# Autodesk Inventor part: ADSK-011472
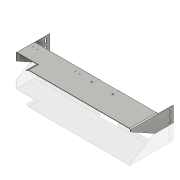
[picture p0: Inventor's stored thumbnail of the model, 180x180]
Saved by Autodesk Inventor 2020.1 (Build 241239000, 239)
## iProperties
Created: 2000-02
Part Number: ADSK-011472
Document SubType Name: Blech
Designer: gpurviance
Material: 1.0312 DC05
Mass: 487.517 g
Surface Area: 3339.23 cm^2
Volume: 487.517 cm^3
Density: 1 g/cm^3
Flat Pattern Width: 25.69 cm
Flat Pattern Length: 92.9572 cm
Flat Pattern Area: 2388.07 cm^2
Sheet Metal Rule: Stahlblech 1.0312 - DC05 -   3.0 mm
Sheet Metal Width: 256,900 mm
Sheet Metal Length: 929,572 mm
Sheet Metal Area: 238806,965 mm^2
Appearance: Stahl
Control State: 0
Master: False
Checked Out: False
Shininess: 60.0
Length Units: 11269
Angle Units: 11279
Time Units: 11290
Mass Units: 11283
Length Display Precision: 3
Angle Display Precision: 2
Compacted: True
Cutlength: 704 SI (20.25 X 34.75)
Material Desc: SHEET,HRS,11 GA
Material_Number: Axxxxxx
Dimensions: 746x97x256,9 mm
Mass: 0,488 kg
G_L: 929,6x256,9 mm
Thickness: 3,000 mm
Semi finished: Stahlblech 1.0312 - DC05 -   3.0 mm
Density: 0.0
Volumn: 0.0
Area: 0.0
PropertySet Name: Model Information
Author: gpurviance
Revision Number: -
Title: ADSK-011472
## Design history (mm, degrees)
node "Face1"
  sketch "Sketch2"
    geometry: L1 (0, 0)-(-746, 0); L2 (-746, 0)-(-746, -168); L3 (-746, -168)-(0, -168); L4 (0, -168)-(0, 0)
    constraints: 8 end point, 2 parallel, 1 horizontal, 1 perpendicular
    dimensions: "d1" = 168 distance between parallel lines of L3 L1; "d2" = 746 distance between parallel lines of L4 L2
node "Extrusion1" dims "d6" = 25.4, "d7" = 0
node "Lasche5"
node "Extrusion2" dims "d15" = 88.9, "d16" = 0
node "Lasche6"
feature "Eckenfase1" dims "d108" = 19, "d109" = 6.35, angle "d110" = 45 deg
node "Extrusion3" dims "d36" = 25.4, "d37" = 0
  sketch "Sketch9"
    geometry: L1 (0, 83.838)-(146, 2.838); L2 (236.9, 78.838)-(236.9, 59.838); L3 (226.9, 59.838)-(226.9, 78.838); L4 (236.9, 37.838)-(236.9, 18.838); L5 (226.9, 18.838)-(226.9, 37.838); L6 (231.9, 78.838)-(231.9, 59.838); L7 (231.9, 37.838)-(231.9, 18.838); L8 (0, 99.838)-(162, 99.838) reference; L9 (0, 2.837)-(0, 93.838) reference; L10 (0, 2.837)-(256.9, 2.838) reference; L11 (256.9, 2.838)-(256.9, 93.838) reference; A1 r 5 centre (231.9, 78.838) between (236.9, 78.838) and (226.9, 78.838); A2 r 5 centre (231.9, 59.838) between (226.9, 59.838) and (236.9, 59.838); A3 r 5 centre (231.9, 37.838) between (236.9, 37.838) and (226.9, 37.838); A4 r 5 centre (231.9, 18.838) between (226.9, 18.838) and (236.9, 18.838)
    constraints: 14 end point, 8 point on circle, 8 tangent, 4 centre point, 4 equal length, 2 point on line, 1 collinear, 1 equal radius
    dimensions: "d27" = 10 diameter of A2; "d38" = 19 distance of L7.start L7.end (= d39); "d39" = 19 distance of L6.start L6.end; "d111" = 16 distance from line of L8 L1.start; "d112" = 146 distance from line of L9 L1.end; "d113" = 25 distance between parallel lines of L11 L6; "d114" = 16 distance from line of L10 L7.end; "d115" = 22 distance of L7.start L6.end
node "Lasche7"
node "Hole1" dims "d48" = 4.134, "d49" = 9.525, "d50" = 6.35, "d51" = 60 deg, "d52" = 19.05, "d53" = 118 deg, "d131" = 10
node "Extrusion5" dims "d63" = 6 (= 2 x Thickness), "d64" = 0
node "Hole2" dims "d68" = 9, "d69" = 9.525, "d70" = 6.35, "d71" = 60 deg, "d72" = 19.05, "d73" = 118 deg, "d134" = 6
node "Volumenkörper1"
node "Volumenkörper"
node "Flächenkörper"
node "Plate1" dims "d87" = 3 (= Thickness)
sketch "Sketch3"
  geometry: L1 (0, 0)-(0, 168) reference; L2 (746, 0)-(0, 0) reference; L3 (0, 0)-(132, 0); L4 (132, 0)-(132, 57); L5 (132, 57)-(0, 57); L6 (0, 57)-(0, 0)
  constraints: 8 end point, 2 parallel, 1 horizontal, 1 perpendicular
  dimensions: "d4" = 132 distance between parallel lines of L1 L4; "d5" = 57 distance between parallel lines of L2 L5
sketch "Sketch6"
  geometry: L1 (-741.5, 93.838)-(-744.5, 93.838) reference; L2 (-744.5, 93.838)-(-744.5, 2.838) reference; L3 (-741.5, 2.838)-(-744.5, 2.838) reference; L4 (-741.5, 93.838)-(-741.5, 2.838) reference; L5 (1.5, 93.837)-(-1.5, 93.837) reference; L6 (-1.5, 93.837)-(-1.5, 2.837) reference; L7 (-1.5, 2.837)-(1.5, 2.837) reference; L8 (1.5, 2.837)-(1.5, 93.837) reference
node "FlatPattern"
sketch "Sketch11"
  geometry: L1 (-9.525, -101.75)-(-9.525, 3.25) reference; L2 (-3.525, 9.25)-(730.475, 9.25) reference; 4 further points
  constraints: 3 horizontal alignment
  dimensions: "d126" = 25 distance of point (42.475, -25.25) point (17.475, -25.25); "d127" = 25 distance of point (296.475, -25.25) point (271.475, -25.25) (= d126); "d128" = 27 distance from line of L1 point (17.475, -25.25); "d129" = 254 distance of point (271.475, -25.25) point (17.475, -25.25); "d130" = 34.5 distance from line of L2 point (17.475, -25.25)
sketch "Sketch13"
  geometry: L1 (209.112, 3.4)-(320.112, 3.4); L2 (320.112, 3.4)-(320.112, 28.4); L3 (320.112, 28.4)-(209.112, 28.4); L4 (209.112, 28.4)-(209.112, 3.4); L5 (-28.888, 22.4)-(-28.888, -68.6) reference; L6 (689.112, 3.4)-(-6.888, 3.4) reference; L7 (-25.888, 28.4)-(708.112, 28.4) reference
  constraints: 8 end point, 2 collinear, 2 parallel, 1 horizontal, 1 perpendicular
  dimensions: "d74" = 111 distance between parallel lines of L2 L4; "d132" = 238 distance between parallel lines of L5 L4
sketch "Sketch14"
  geometry: L1 (-354.037, 125.5)-(-227.037, 125.5); L2 (-235.038, 162)-(-346.038, 162) reference; L3 (-235.038, 168)-(-0.037, 168) reference; 2 further points
  constraints: 2 end point, 2 midpoint, 1 horizontal, 1 horizontal alignment, 1 vertical alignment
  dimensions: "d67" = 127 distance of L1.end L1.start; "d133" = 42.5 distance between parallel lines of L3 L1
sketch "Skizze15"
  geometry: L1 through (0, 55.5) direction (2.66e-32, -1); L2 through (48.5, 0) direction (1, -7.5e-34); L3 (97, 0)-(97, 111); L4 (97, 111)-(0, 111)
  constraints: 6 end point, 1 horizontal, 1 perpendicular, 1 vertical
feature "Grobblech6" dims "d87" = 3 (= Thickness), "d88" = 3 (= BendReliefWidth), "d89" = 1.5 (= BendReliefDepth), "d90" = 6 (= MinimumRemnant), "d91" = 3 (= TransitionRadius), "d92" = 97, "d93" = 90 deg, "d94" = 3 (= BendRadius), "d95" = 12 (= CornerReliefSize), "d96" = 3 (= Abstandsgröße), "d97" = 3 (= JacobiRadiusGröße), "SeamGap" = 0.00508
feature "Biegung5" dims "d87" = 3 (= Thickness), "d88" = 3 (= BendReliefWidth), "d89" = 1.5 (= BendReliefDepth), "d90" = 6 (= MinimumRemnant), "d91" = 3 (= TransitionRadius), "d92" = 97, "d93" = 90 deg, "d94" = 3 (= BendRadius), "SeamGap" = 0.00508
feature "Ecke1" dims "d92" = 97, "d93" = 90 deg, "d95" = 12 (= CornerReliefSize), "d96" = 3 (= Abstandsgröße), "d97" = 3 (= JacobiRadiusGröße)
node "Projizierte Kontur1"
node "Projizierte Kontur2"
sketch "Skizze16"
  geometry: L1 through (367, 0) direction (-1, -2.38e-34); L2 through (0, -12.5) direction (0, -1); L3 (0, -25)-(734, -25); L4 (734, -25)-(734, 0)
  constraints: 6 end point, 1 horizontal, 1 perpendicular, 1 vertical
feature "Grobblech7" dims "d87" = 3 (= Thickness), "d98" = 3 (= BendReliefWidth), "d99" = 1.5 (= BendReliefDepth), "d100" = 6 (= MinimumRemnant), "d101" = 3 (= TransitionRadius), "d102" = 25, "d103" = 90 deg, "d104" = 3 (= BendRadius), "d105" = 12 (= CornerReliefSize), "d106" = 3 (= Abstandsgröße), "d107" = 3 (= JacobiRadiusGröße), "SeamGap" = 0.00508
feature "Biegung6" dims "d87" = 3 (= Thickness), "d98" = 3 (= BendReliefWidth), "d99" = 1.5 (= BendReliefDepth), "d100" = 6 (= MinimumRemnant), "d101" = 3 (= TransitionRadius), "d102" = 25, "d103" = 90 deg, "d104" = 3 (= BendRadius), "SeamGap" = 0.00508
feature "Ecke2" dims "d102" = 25, "d103" = 90 deg, "d105" = 12 (= CornerReliefSize), "d106" = 3 (= Abstandsgröße), "d107" = 3 (= JacobiRadiusGröße)
sketch "Skizze17"
  geometry: L1 (0, 57)-(0, 3); L2 (0, 3)-(16, 3); L3 (16, 3)-(16, 57); L4 (16, 57)-(0, 57)
  constraints: 8 end point
feature "Grobblech8" dims "d87" = 3 (= Thickness), "d116" = 3 (= BendReliefWidth), "d117" = 1.5 (= BendReliefDepth), "d118" = 6 (= MinimumRemnant), "d119" = 3 (= TransitionRadius), "d120" = 16, "d121" = 30 deg, "d122" = 3 (= BendRadius), "d123" = 12 (= CornerReliefSize), "d124" = 3 (= Abstandsgröße), "d125" = 3 (= JacobiRadiusGröße), "SeamGap" = 0.00508
feature "Biegung7" dims "d87" = 3 (= Thickness), "d116" = 3 (= BendReliefWidth), "d117" = 1.5 (= BendReliefDepth), "d118" = 6 (= MinimumRemnant), "d119" = 3 (= TransitionRadius), "d120" = 16, "d121" = 30 deg, "d122" = 3 (= BendRadius), "SeamGap" = 0.00508
feature "Ecke3" dims "d120" = 16, "d121" = 30 deg, "d123" = 12 (= CornerReliefSize), "d124" = 3 (= Abstandsgröße), "d125" = 3 (= JacobiRadiusGröße)
feature "ExtrusionAbwicklung2" dims "d0" = 3 (derived)
other parameters: "Thickness" = 3 (derived), "BendRadius" = 3 (= Thickness), "BendReliefWidth" = 3 (= Thickness), "BendReliefDepth" = 1.5 (= 0.5 x Thickness), "CornerReliefSize" = 12 (= 4 x Thickness), "MinimumRemnant" = 6 (= 2 x Thickness), "d3" = 3 (= BendRadius), "d8" = 96.8375, "d9" = 90 deg, "d10" = 3 (= BendRadius), "d11" = 96.8375, "d12" = 90 deg, "d13" = 3 (= BendRadius), "d18" = 25.4, "d19" = 90 deg, "d20" = 3 (= BendRadius), "d40" = 15.875, "d41" = 30 deg, "d42" = 3 (= BendRadius), "TransitionRadius" = 3 (= BendRadius), "JacobiRadiusGröße" = 3 (= BendRadius), "Abstandsgröße" = 3 (= Thickness)
